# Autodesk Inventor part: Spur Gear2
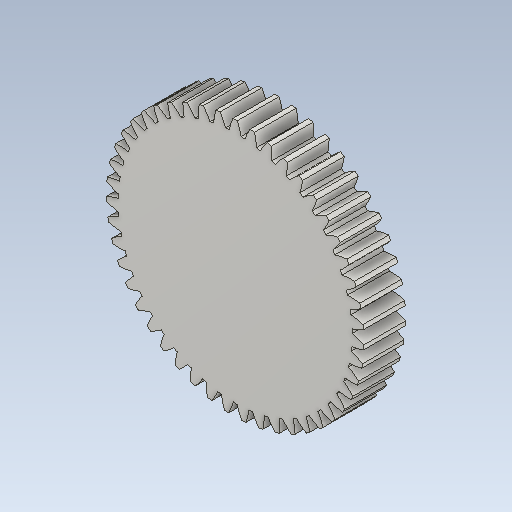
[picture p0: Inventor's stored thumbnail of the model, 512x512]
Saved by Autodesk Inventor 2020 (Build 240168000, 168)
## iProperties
CustomPartVersion: 1
Created: 2019-09
Part Number: Spur Gear2
Material: Steel
Document SubType Name: Modeling
Designer: user
Categories: <?xml version="1.0" encoding="UTF-16"?> <MemberInstance><Categories><FamilyTemplate><FamilyTemplateParameter ValueType="xs:double" Id="1" ObjectReferenceKey="da
Density: 7.85 g/cm^3
Appearance: Steel
Mass: 215.325 g
Surface Area: 92.0847 cm^2
Volume: 27.43 cm^3
Author: user
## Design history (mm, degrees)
sketch "Sketch1"
  geometry: C1 r 30.875 at (0, 0)
  constraints: 1 centre point
  dimensions: "d0" = 61.75 diameter of C1 (= da_da)
extrude "Extrusion1" new body sketch "Sketch1" distance "d1" = 10 (= da_b); taper "d2" = 0 deg
workplane "Work Plane2"
sketch "Sketch2"
  geometry: C1 r 30.875 at (0, 0) reference; C2 r 29.543 at (0, 0)
  constraints: 1 centre point, 1 coincident
  dimensions: "d3" = 59.08571 diameter of C2 (= da_dw)
feature "Pitch Diameter" sketch "Sketch2" dims "d4" = 10, "d5" = 0
workplane "Work Plane8"
workplane "Work Plane9"
feature "Spur Gear" dims "da_b" = 10, "da_d" = 58.75, "da_aw" = 44, "da_da" = 61.75, "da_df" = 56.14567, "da_dw" = 59.08571, angle "da_beta" = 0 deg, "da_lefttooth" = 0, "da_righttooth" = 0
body "Solid1"
body "Srf1"
other parameters: "d16" = 44 (= da_aw), "d17" = 0, "d34" = 0.66842 (computed from da_z), "d39" = 0, "d41" = 0, "d43" = 44 (= da_aw), "d46" = 44 (= da_aw), "d47" = 0, "d48" = 0
